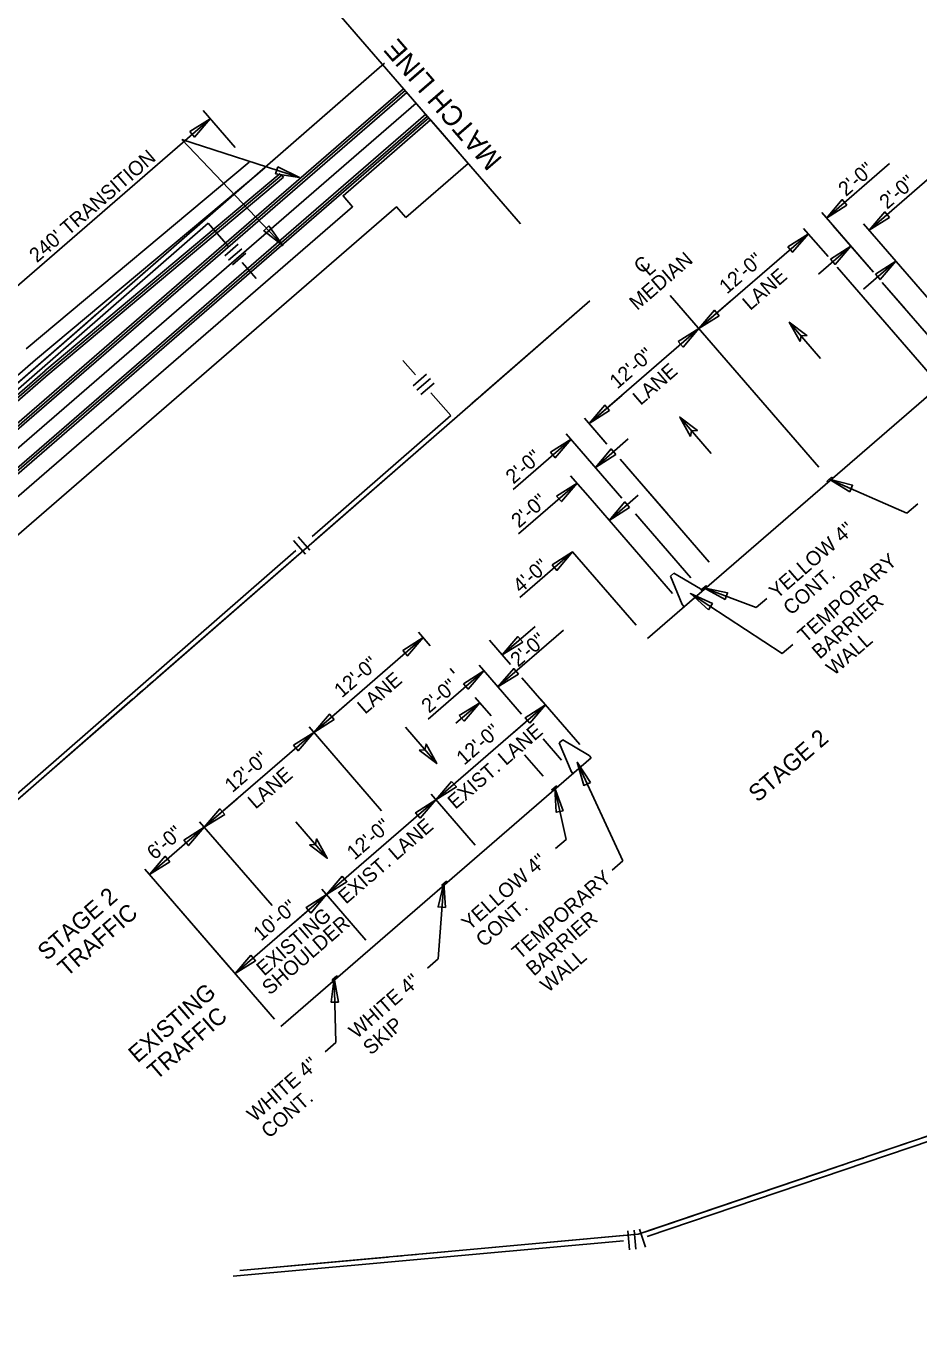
# Model space of a CAD drawing. Extents: x 259983 to 267998, y 211467 to 219827.
# Drawn here: x 263253 to 263992, y 216417 to 217501 of the extents above; entities that cross this region are included whole.
import ezdxf

# ---------------------------------------------------------------- set-up
doc = ezdxf.new("R2010")
doc.units = 0
for name, color, linetype in [('1', 7, 'Continuous'), ('Default', 7, 'Continuous'), ('Level 43', 7, 'Continuous'), ('Level 58', 7, 'Continuous'), ('R-W - CofA', 7, 'Continuous'), ('R_MOT STAGE 1', 7, 'Continuous'), ('R_MOT STAGE 2', 7, 'Continuous'), ('STATIONING1', 7, 'Continuous')]:
    doc.layers.add(name, color=color, linetype=linetype)

msp = doc.modelspace()

# ---------------------------------------------------------------- linework, layer by layer
at = {"layer": '1'}
for p, q in [((263381.6, 217407.5), (263479, 217375.9)), ((263381.6, 217407.5), (263465.2, 217319.5)), ((263967.7, 217387.4), (263915.7, 217342.4)), ((264001.1, 217375.6), (263951, 217332.2)), ((263954.5, 217297.5), (263911.7, 217346.9)), ((263916.9, 217310.4), (263896.6, 217333.8)), ((263954.2, 217297.9), (263921.3, 217335.9)), ((264022.4, 217249.7), (263946.2, 217337.7)), ((263809.8, 217250.8), (263900.6, 217329.3)), ((263909.1, 217296), (263935.8, 217319.1)), ((263999.9, 217214.6), (263924.5, 217301.7)), ((263946.4, 217283.4), (263973.1, 217306.6)), ((264015, 217227.7), (263961.8, 217289.1)), ((263980.8, 217267.2), (263961.8, 217289.1)), ((263909.2, 217136.1), (263786.1, 217278.2)), ((263837, 217274.3), (263809.8, 217250.8)), ((263719.1, 217172.2), (263809.8, 217250.8)), ((263746.3, 217195.8), (263719.1, 217172.2)), ((263746.3, 217195.8), (263719.1, 217172.2)), ((263733.8, 217155.2), (263715.2, 217176.7)), ((263732.4, 217156.8), (263715.2, 217176.7)), ((263656, 217117.6), (263704, 217159.1)), ((263746.2, 217110.4), (263700.1, 217163.7)), ((263751.4, 217159.4), (263724.2, 217135.8)), ((263818.4, 217057.5), (263744.6, 217142.7)), ((263719.8, 217110.3), (263703.6, 217129)), ((263784.2, 217097), (263749.7, 217136.9)), ((263660.5, 217080.8), (263709, 217122.7)), ((263982.3, 217098), (263917.8, 217126)), ((263788.2, 217031.3), (263719.8, 217110.3)), ((263759.7, 217112.9), (263735.6, 217092)), ((263991.2, 217105.7), (263982.3, 217098)), ((263803.3, 217044.4), (263757.5, 217097.3)), ((263705.3, 217065.9), (263661.7, 217028.1)), ((263757.9, 217005.1), (263705.3, 217065.9)), ((263879, 216981.6), (263802.9, 217031.3)), ((263857.3, 217019.8), (263814.1, 217036.2)), ((263866.2, 217027.4), (263857.3, 217019.8)), ((263587.4, 216988.2), (263577.7, 216999.5)), ((263697.8, 217001.1), (263643.5, 216954)), ((263674.2, 217004.1), (263647, 216980.5)), ((263490.9, 216916.4), (263581.6, 216994.9)), ((263653.8, 216972.7), (263636.4, 216992.8)), ((263887.8, 216989.3), (263879, 216981.6)), ((263585.6, 216927.4), (263631.9, 216967.4)), ((263607.1, 216965.5), (263603.9, 216969.2)), ((263662.9, 216931.6), (263628, 216972)), ((263679.9, 216942.6), (263663.3, 216961.7)), ((263637.9, 216930), (263624.7, 216945.2)), ((263711.2, 216906.4), (263678.9, 216943.6)), ((263518.1, 216939.9), (263490.9, 216916.4)), ((263682.9, 216939.1), (263592.1, 216860.6)), ((263608.6, 216923.9), (263628.4, 216940.9)), ((263655.6, 216915.5), (263682.9, 216939.1)), ((263547.1, 216851.4), (263487, 216920.9)), ((263400.2, 216837.8), (263490.9, 216916.4)), ((263696.1, 216893.3), (263680.8, 216911)), ((263680.9, 216880.2), (263665.6, 216897.9)), ((263747, 216809.9), (263709.1, 216891.7)), ((263700, 216827.8), (263690.5, 216869.9)), ((263427.4, 216861.4), (263400.2, 216837.8)), ((263427.4, 216861.4), (263400.2, 216837.8)), ((263592.1, 216860.6), (263501.4, 216782)), ((263624.7, 216822.9), (263588.2, 216865.1)), ((263354.8, 216798.6), (263400.2, 216837.8)), ((263456.4, 216772.9), (263396.3, 216842.4)), ((263691.1, 216820.1), (263700, 216827.8)), ((263422.8, 216720), (263350.9, 216803.1)), ((263458.4, 216678.9), (263350.9, 216803.1)), ((263738.2, 216802.2), (263747, 216809.9)), ((263593.9, 216728.8), (263598.6, 216791.4)), ((263501.4, 216782), (263425.8, 216716.6)), ((263474.2, 216758.5), (263501.4, 216782)), ((263534, 216744.4), (263497.5, 216786.6)), ((263585.1, 216721.2), (263593.9, 216728.8)), ((263509.2, 216659.5), (263507.9, 216712.8)), ((263500.3, 216651.8), (263509.2, 216659.5))]:
    msp.add_line(p, q, dxfattribs=at)
for points in [[(263388.3, 217413.9), (263405.2, 217424.6), (263392.2, 217409.4)], [(263461.1, 217384.8), (263479, 217375.9), (263459.2, 217379.1)], [(263932.6, 217353.1), (263915.7, 217342.4), (263928.7, 217357.6)], [(263967.9, 217342.9), (263951, 217332.2), (263964, 217347.4)], [(263453.8, 217336), (263465.2, 217319.5), (263449.4, 217331.9)], [(263883.6, 217318.6), (263900.6, 217329.3), (263887.5, 217314.1)], [(263918.9, 217308.4), (263935.8, 217319.1), (263922.8, 217303.9)], [(263956.2, 217295.9), (263973.1, 217306.6), (263960.1, 217291.4)], [(263826.8, 217261.4), (263809.8, 217250.8), (263822.8, 217266)], [(263792.9, 217240.1), (263809.8, 217250.8), (263796.8, 217235.5)], [(263736, 217182.9), (263719.1, 217172.2), (263732.1, 217187.4)], [(263736, 217182.9), (263719.1, 217172.2), (263732.1, 217187.4)], [(263687, 217148.4), (263704, 217159.1), (263691, 217143.9)], [(263741.1, 217146.5), (263724.2, 217135.8), (263737.2, 217151.1)], [(263692.1, 217112), (263709, 217122.7), (263696, 217107.5)], [(263934.9, 217115.6), (263917.8, 217126), (263937.2, 217121.1)], [(263752.5, 217102.7), (263735.6, 217092), (263748.6, 217107.3)], [(263688.4, 217055.2), (263705.3, 217065.9), (263692.3, 217050.6)], [(263817.9, 217018), (263802.9, 217031.3), (263821.2, 217023)], [(263831.6, 217026.5), (263814.1, 217036.2), (263833.7, 217032.1)], [(263564.7, 216984.2), (263581.6, 216994.9), (263568.6, 216979.7)], [(263664, 216991.2), (263647, 216980.5), (263660, 216995.7)], [(263615, 216956.7), (263631.9, 216967.4), (263618.9, 216952.2)], [(263660.4, 216964.7), (263643.5, 216954), (263656.5, 216969.3)], [(263507.8, 216927.1), (263490.9, 216916.4), (263503.9, 216931.6)], [(263611.4, 216930.3), (263628.4, 216940.9), (263615.4, 216925.7)], [(263669.9, 216923.9), (263682.9, 216939.1), (263665.9, 216928.4)], [(263474, 216905.7), (263490.9, 216916.4), (263477.9, 216901.2)], [(263720.1, 216875), (263709.1, 216891.7), (263714.6, 216872.5)], [(263605.1, 216875.8), (263592.1, 216860.6), (263609.1, 216871.3)], [(263697.6, 216851.5), (263690.5, 216870.2), (263691.8, 216850.2)], [(263579.1, 216845.3), (263592.1, 216860.6), (263575.2, 216849.9)], [(263417.1, 216848.5), (263400.2, 216837.8), (263413.2, 216853.1)], [(263417.1, 216848.5), (263400.2, 216837.8), (263413.2, 216853.1)], [(263383.2, 216827.1), (263400.2, 216837.8), (263387.2, 216822.6)], [(263371.8, 216809.3), (263354.8, 216798.6), (263367.8, 216813.8)], [(263514.4, 216797.2), (263501.4, 216782), (263518.3, 216792.7)], [(263599.9, 216771.4), (263598.6, 216791.4), (263593.9, 216771.9)], [(263488.4, 216766.8), (263501.4, 216782), (263484.5, 216771.3)], [(263438.8, 216731.8), (263425.8, 216716.6), (263442.7, 216727.3)], [(263511.3, 216693.1), (263507.9, 216712.8), (263505.3, 216693)]]:
    msp.add_lwpolyline(points, close=True, dxfattribs=at)
at = {"layer": 'Default'}
for p, q in [((263786.4, 217045.8), (263789.2, 217048.2)), ((263796.1, 217022.2), (263786.4, 217045.8)), ((263811.2, 217035.3), (263789.2, 217048.2)), ((263812.8, 217033.4), (263811.2, 217035.3)), ((263797.7, 217020.3), (263796.1, 217022.2)), ((263694.3, 216907.8), (263697.1, 216910.2)), ((263719.1, 216897.3), (263697.1, 216910.2)), ((263704, 216884.2), (263694.3, 216907.8)), ((263720.7, 216895.4), (263463.7, 216672.8)), ((263720.7, 216895.4), (263719.1, 216897.3)), ((263705.6, 216882.3), (263703.9, 216884.2)), ((263705.6, 216882.3), (263704, 216884.2))]:
    msp.add_line(p, q, dxfattribs=at)
for points in [[(263915.9, 217124.3), (263919.7, 217127.7), (263920.6, 217126.7), (263916.7, 217123.4)], [(263812.2, 217034.6), (263816, 217037.9), (263816.9, 217036.9), (263813, 217033.6)], [(263692, 216872.2), (263688.1, 216868.9), (263689, 216867.9), (263692.8, 216871.2)], [(263600.8, 216793.3), (263597, 216790), (263597.8, 216789), (263601.7, 216792.3)], [(263510.1, 216714.8), (263506.2, 216711.4), (263507.1, 216710.4), (263510.9, 216713.8)]]:
    msp.add_lwpolyline(points, close=True, dxfattribs=at)
at = {"layer": 'Level 43'}
for points in [[(263884.8, 217256.1), (263910.8, 217226.1)], [(263794.1, 217177.5), (263820.1, 217147.5)], [(263592.8, 216890.6), (263566.8, 216920.7)], [(263502.1, 216812.1), (263476.1, 216842.2)]]:
    msp.add_lwpolyline(points, dxfattribs=at)
at = {"layer": 'Level 58'}
for points in [[(263893.8, 217240), (263884.8, 217256.1), (263899.4, 217245), (263894.6, 217244.8)], [(263803.1, 217161.5), (263794.1, 217177.5), (263808.7, 217166.4), (263803.9, 217166.2)], [(263578.2, 216901.8), (263592.8, 216890.6), (263583.9, 216906.7), (263583, 216902)], [(263487.4, 216823.3), (263502.1, 216812.1), (263493.1, 216828.2), (263492.2, 216823.5)]]:
    msp.add_lwpolyline(points, close=True, dxfattribs=at)
at = {"layer": 'R-W - CofA'}
for p, q in [((263403.3, 217338), (263420.2, 217318.7)), ((263417.1, 217311.1), (263428.2, 217320.7)), ((263420.3, 217307.4), (263431.4, 217317)), ((263423.5, 217303.7), (263434.6, 217313.3)), ((263431.6, 217305.6), (263443.1, 217292.4)), ((263575.1, 217212.4), (263564.7, 217224.4)), ((263573.2, 217203.4), (263584.3, 217213.1)), ((263576.4, 217199.7), (263587.5, 217209.4)), ((263579.6, 217196.1), (263590.7, 217205.7)), ((263604.4, 217178.8), (263587.9, 217197.7)), ((263474.2, 217075.2), (263484, 217064)), ((263478, 217078.4), (263487.7, 217067.2)), ((263429.6, 216470.8), (263759.5, 216500.7)), ((263751.1, 216503.6), (263752.5, 216487.9)), ((263756.3, 216504.1), (263757.7, 216488.3)), ((263760.6, 216505), (263765.7, 216490))]:
    msp.add_line(p, q, dxfattribs=at)
for points in [[(262530.1, 216582.3), (263549.4, 217470.5)], [(263443.9, 217378.6), (263549.4, 217470.5)], [(263323.3, 217273.4), (263443.9, 217378.6)], [(263189.3, 217151.5), (263403.3, 217338)], [(262694.2, 216380.4), (263719.6, 217273.9)], [(263315, 217266.2), (263319.5, 217270.2)], [(263630.1, 217195.9), (263719.6, 217273.9)], [(263306.8, 217259.1), (263311.3, 217263)], [(263186.7, 217154.5), (263303.1, 217255.8)], [(263759.5, 216500.7), (264072.6, 216606.9), (264334.3, 216834.9), (264287.8, 216895.1), (264704.6, 217224)], [(263621.8, 217188.7), (263626.3, 217192.6)], [(263613.5, 217181.4), (263618, 217185.4)], [(263489.5, 217078.7), (263604.4, 217178.8)], [(263492.1, 217075.7), (263609.7, 217178.1)], [(263220.6, 216844.3), (263476.1, 217067)], [(263361.1, 216961.6), (263478.7, 217064)], [(263352.8, 216954.3), (263357.4, 216958.3)], [(263223.1, 216841.3), (263340.7, 216943.8)], [(263344.5, 216947.1), (263349, 216951)], [(263767.1, 216498.8), (264074.7, 216603.1), (264108.9, 216632.9)], [(263951, 216565.6), (264072.6, 216606.9), (264106.1, 216636.1)], [(263939.8, 216561.8), (263945.9, 216563.9)], [(263765.8, 216502.8), (263923.6, 216556.3)], [(263928.7, 216558.1), (263934.8, 216560.1)], [(263581.2, 216484.5), (263747.2, 216499.6)], [(263424.1, 216466.1), (263747.6, 216495.4)], [(263429.6, 216470.8), (263552.4, 216481.9)], [(263557.7, 216482.4), (263564.1, 216483)], [(263569.5, 216483.5), (263575.9, 216484.1)]]:
    msp.add_lwpolyline(points, dxfattribs=at)
at = {"layer": 'R_MOT STAGE 1'}
for p, q in [((263662.2, 217337.5), (263495.2, 217530.4)), ((263565.3, 217449.4), (263098.2, 217045.1)), ((263566.6, 217447.9), (263099.5, 217043.5)), ((263567.9, 217446.4), (263100.8, 217042)), ((263565.3, 217449.4), (263565.3, 217449.4)), ((263566.6, 217447.9), (263566.6, 217447.9)), ((263567.9, 217446.4), (263567.9, 217446.4)), ((263575.8, 217437.4), (263108.7, 217033)), ((263583.6, 217428.3), (263116.5, 217023.9)), ((263585, 217426.8), (263117.8, 217022.4)), ((263586.3, 217425.3), (263119.1, 217020.9)), ((263583.6, 217428.3), (263583.6, 217428.3)), ((263585, 217426.8), (263584.9, 217426.8)), ((263586.3, 217425.3), (263586.3, 217425.2)), ((263252.7, 217234.1), (263437.4, 217388.6)), ((263260.4, 217224.9), (263444.5, 217379)), ((263268.1, 217215.7), (263463.2, 217379.3)), ((263269.4, 217214.2), (263464.5, 217377.8)), ((263270.7, 217212.6), (263465.8, 217376.2)), ((263444.5, 217379), (263450.3, 217384)), ((263464.5, 217377.8), (263465.8, 217376.2)), ((262747.9, 216781.2), (263260.4, 217224.9)), ((262755.7, 216772.1), (263268.3, 217215.8)), ((262757.1, 216770.6), (263269.6, 217214.3)), ((262758.4, 216769.1), (263270.9, 217212.8))]:
    msp.add_line(p, q, dxfattribs=at)
at = {"layer": 'R_MOT STAGE 2'}
for p, q in [((263767.4, 216994.1), (264402.6, 217543.9)), ((263425.8, 217400.8), (263399.2, 217431.5)), ((263405.2, 217424.6), (263223.8, 217267.5))]:
    msp.add_line(p, q, dxfattribs=at)
msp.add_lwpolyline([(263567.1, 217342.8), (263559.5, 217351.6), (263145, 216992.7), (263129.3, 217010.9), (263523.1, 217351.7), (263515.2, 217360.8), (263587.5, 217423.8), (263595.6, 217414.5), (263618.9, 217387.6)], close=True, dxfattribs=at)

# ---------------------------------------------------------------- texts
at = {"layer": '1'}
for s, height, rotation, p in [("240' TRANSITION", 12, 40.8733, (263261.6, 217304.9)), ('2\'-0"', 12, 40.8733, (263931.8, 217359.7)), ('2\'-0"', 12, 40.8733, (263965.9, 217349.1)), ('MEDIAN', 12, 40.8733, (263758.8, 217265.4)), ('12\'-0"', 12, 40.8833, (263833.2, 217278.9)), ('C', 12, 40.8733, (263762.5, 217295.5)), ('L', 12, 40.8733, (263768.3, 217293.6)), ('LANE', 12, 40.8833, (263852.4, 217265.3)), ('12\'-0"', 12, 40.8833, (263742.4, 217200.3)), ('LANE', 12, 40.8833, (263761.6, 217186.7)), ('2\'-0"', 12, 40.8833, (263656.3, 217121.5)), ('2\'-0"', 12, 40.8733, (263660.9, 217085.1)), ('YELLOW 4"', 12, 40.8833, (263874.5, 217026.4)), ('TEMPORARY', 12, 40.8833, (263898.2, 216990.1)), ('4\'-0"', 12, 40.8733, (263662.3, 217031.2)), ('CONT.', 12, 40.8833, (263886.2, 217012.8)), ('BARRIER', 12, 40.8833, (263910, 216976.5)), ('2\'-0"', 12, 40.8733, (263660.2, 216970)), ('WALL', 12, 40.8833, (263921.8, 216962.9)), ('12\'-0"', 12, 40.8833, (263514.2, 216944.5)), ('LANE', 12, 40.8833, (263533.4, 216930.9)), ('2\'-0"', 12, 40.8733, (263586.5, 216931.8)), ('EXIST. LANE', 12, 40.8833, (263608.2, 216852.2)), ('12\'-0"', 12, 40.8833, (263615.5, 216888.7)), ('STAGE 2', 14, 40.8733, (263858.6, 216857.9)), ('12\'-0"', 12, 40.8833, (263423.5, 216866)), ('LANE', 12, 40.8833, (263442.7, 216852.3)), ('EXIST. LANE', 12, 40.8833, (263517.5, 216773.6)), ('12\'-0"', 12, 40.8833, (263524.7, 216810.2)), ('6\'-0"', 12, 40.8833, (263359.1, 216810.2)), ('YELLOW 4"', 12, 40.8833, (263619.8, 216751.7)), ('TEMPORARY', 12, 40.8833, (263661.5, 216727.7)), ('STAGE 2', 14, 40.8733, (263269.7, 216726.8)), ('TRAFFIC', 14, 40.8733, (263286.4, 216713.5)), ('10\'-0"', 12, 40.8833, (263447.2, 216743)), ('EXISTING', 12, 40.8833, (263449.8, 216714.1)), ('CONT.', 12, 40.8833, (263631.6, 216738)), ('SHOULDER', 12, 40.8833, (263454.5, 216698.3)), ('BARRIER', 12, 40.8833, (263673.2, 216714)), ('WALL', 12, 40.8833, (263685, 216700.4)), ('WHITE 4"', 12, 40.8833, (263526.4, 216662.2)), ('EXISTING', 14, 40.8733, (263344.9, 216642.1)), ('TRAFFIC', 14, 40.8733, (263360.6, 216627.9)), ('SKIP', 12, 40.8833, (263538.2, 216648.6)), ('WHITE 4"', 12, 40.8833, (263442, 216593.2)), ('CONT.', 12, 40.8833, (263453.8, 216579.6))]:
    msp.add_text(s, height=height, rotation=rotation, dxfattribs=at).set_placement(p)
at = {"layer": 'STATIONING1'}
msp.add_text('MATCH LINE', height=16.5, rotation=130.8833, dxfattribs=at).set_placement((263647.8, 217391.1))

doc.saveas('drawing.dxf')
